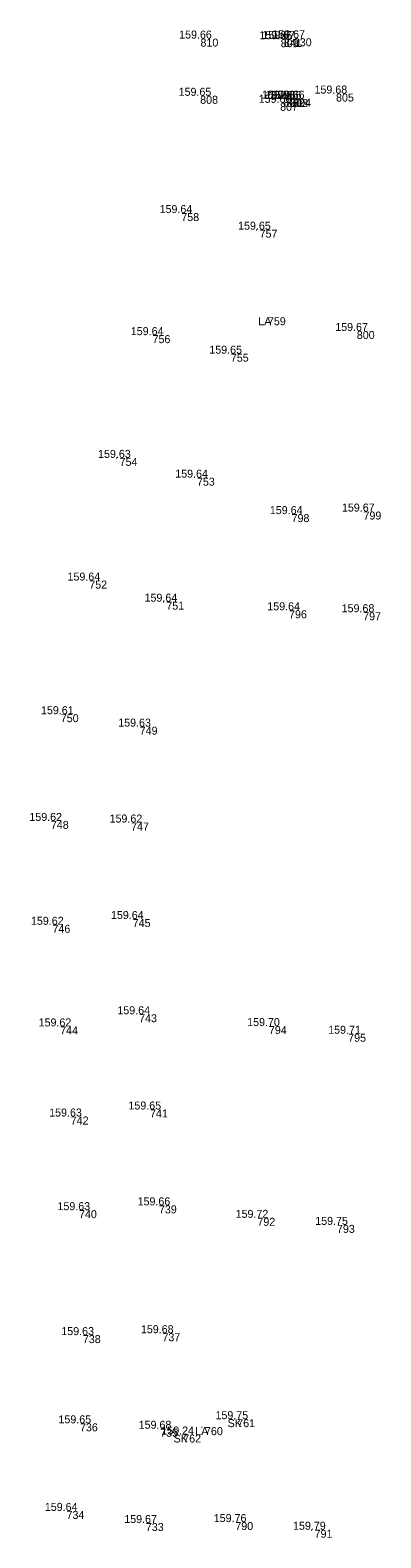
# Model space of a CAD drawing. Extents: x -583198 to -582878, y -1211024 to -1210637.
# Drawn here: x -582888.5 to -582877.53, y -1210734.46 to -1210687.29 of the extents above; entities that cross this region are included whole.
import ezdxf

# ---------------------------------------------------------------- set-up
doc = ezdxf.new("R2010")
doc.units = 0
for name, color, linetype in [('1   Kódy', 7, 'Continuous'), ('4   Body podrobné', 7, 'Continuous'), ('5   Body podrobné - čísla', 7, 'Continuous'), ('6   Body podrobné - výšky', 7, 'Continuous')]:
    doc.layers.add(name, color=color, linetype=linetype)

msp = doc.modelspace()

# ---------------------------------------------------------------- linework, layer by layer
at = {"layer": '4   Body podrobné'}
for p, q in [((-582883.26, -1210687.55), (-582883.259, -1210687.55)), ((-582880.75, -1210687.57), (-582880.749, -1210687.57)), ((-582880.65, -1210687.56), (-582880.649, -1210687.56)), ((-582880.34, -1210687.54), (-582880.339, -1210687.54)), ((-582883.27, -1210689.34), (-582883.269, -1210689.34)), ((-582880.77, -1210689.56), (-582880.769, -1210689.56)), ((-582880.67, -1210689.43), (-582880.669, -1210689.43)), ((-582880.56, -1210689.44), (-582880.559, -1210689.44)), ((-582880.45, -1210689.44), (-582880.449, -1210689.44)), ((-582880.36, -1210689.43), (-582880.359, -1210689.43)), ((-582879.02, -1210689.27), (-582879.019, -1210689.27)), ((-582883.86, -1210693.01), (-582883.859, -1210693.01)), ((-582881.41, -1210693.53), (-582881.409, -1210693.53)), ((-582881.15, -1210696.27), (-582881.149, -1210696.27)), ((-582878.37, -1210696.7), (-582878.369, -1210696.7)), ((-582884.76, -1210696.83), (-582884.759, -1210696.83)), ((-582882.31, -1210697.41), (-582882.309, -1210697.41)), ((-582885.79, -1210700.67), (-582885.789, -1210700.67)), ((-582883.37, -1210701.29), (-582883.369, -1210701.29)), ((-582878.16, -1210702.35), (-582878.159, -1210702.35)), ((-582880.41, -1210702.43), (-582880.409, -1210702.43)), ((-582886.74, -1210704.51), (-582886.739, -1210704.51)), ((-582884.33, -1210705.17), (-582884.329, -1210705.17)), ((-582880.49, -1210705.44), (-582880.489, -1210705.44)), ((-582878.17, -1210705.5), (-582878.169, -1210705.5)), ((-582887.63, -1210708.69), (-582887.629, -1210708.69)), ((-582885.16, -1210709.08), (-582885.159, -1210709.08)), ((-582887.94, -1210712.03), (-582887.939, -1210712.03)), ((-582885.43, -1210712.08), (-582885.429, -1210712.08)), ((-582885.38, -1210715.1), (-582885.379, -1210715.1)), ((-582887.89, -1210715.28), (-582887.889, -1210715.28)), ((-582885.18, -1210718.08), (-582885.179, -1210718.08)), ((-582887.65, -1210718.46), (-582887.649, -1210718.46)), ((-582881.12, -1210718.45), (-582881.119, -1210718.45)), ((-582878.64, -1210718.69), (-582878.639, -1210718.69)), ((-582884.84, -1210721.06), (-582884.839, -1210721.06)), ((-582887.32, -1210721.28), (-582887.319, -1210721.28)), ((-582884.56, -1210724.06), (-582884.559, -1210724.06)), ((-582887.06, -1210724.21), (-582887.059, -1210724.21)), ((-582881.48, -1210724.45), (-582881.479, -1210724.45)), ((-582878.99, -1210724.67), (-582878.989, -1210724.67)), ((-582886.94, -1210728.12), (-582886.939, -1210728.12)), ((-582884.45, -1210728.06), (-582884.449, -1210728.06)), ((-582887.03, -1210730.88), (-582887.029, -1210730.88)), ((-582884.52, -1210731.05), (-582884.519, -1210731.05)), ((-582883.12, -1210731), (-582883.119, -1210731)), ((-582882.11, -1210730.75), (-582882.109, -1210730.75)), ((-582883.8, -1210731.23), (-582883.799, -1210731.23)), ((-582887.45, -1210733.62), (-582887.449, -1210733.62)), ((-582882.17, -1210733.97), (-582882.169, -1210733.97)), ((-582884.97, -1210734), (-582884.969, -1210734)), ((-582879.69, -1210734.21), (-582879.689, -1210734.21))]:
    msp.add_line(p, q, dxfattribs=at)

# ---------------------------------------------------------------- texts
at = {"layer": '1   Kódy'}
for s, p in [('LA', (-582881.36, -1210696.52)), ('LA', (-582883.33, -1210731.25)), ('SK', (-582882.319, -1210731)), ('SK', (-582884.009, -1210731.48))]:
    msp.add_text(s, height=0.25, dxfattribs=at).set_placement(p)
at = {"layer": '5   Body podrobné - čísla'}
for s, p in [(' 810', (-582883.26, -1210687.8)), (' 809', (-582880.75, -1210687.82)), (' 841', (-582880.65, -1210687.81)), (' 830', (-582880.34, -1210687.79)), (' 808', (-582883.27, -1210689.59)), (' 807', (-582880.77, -1210689.81)), (' 801', (-582880.67, -1210689.68)), (' 802', (-582880.56, -1210689.69)), (' 803', (-582880.45, -1210689.69)), (' 804', (-582880.36, -1210689.68)), (' 805', (-582879.02, -1210689.52)), (' 758', (-582883.86, -1210693.26)), (' 757', (-582881.41, -1210693.78)), (' 759', (-582881.15, -1210696.52)), (' 800', (-582878.37, -1210696.95)), (' 756', (-582884.76, -1210697.08)), (' 755', (-582882.31, -1210697.66)), (' 754', (-582885.79, -1210700.92)), (' 753', (-582883.37, -1210701.54)), (' 799', (-582878.16, -1210702.6)), (' 798', (-582880.41, -1210702.68)), (' 752', (-582886.74, -1210704.76)), (' 751', (-582884.33, -1210705.42)), (' 796', (-582880.49, -1210705.69)), (' 797', (-582878.17, -1210705.75)), (' 750', (-582887.63, -1210708.94)), (' 749', (-582885.16, -1210709.33)), (' 748', (-582887.94, -1210712.28)), (' 747', (-582885.43, -1210712.33)), (' 745', (-582885.38, -1210715.35)), (' 746', (-582887.89, -1210715.53)), (' 743', (-582885.18, -1210718.33)), (' 744', (-582887.65, -1210718.71)), (' 794', (-582881.12, -1210718.7)), (' 795', (-582878.64, -1210718.94)), (' 741', (-582884.84, -1210721.31)), (' 742', (-582887.32, -1210721.53)), (' 739', (-582884.56, -1210724.31)), (' 740', (-582887.06, -1210724.46)), (' 792', (-582881.48, -1210724.7)), (' 793', (-582878.99, -1210724.92)), (' 738', (-582886.94, -1210728.37)), (' 737', (-582884.45, -1210728.31)), (' 736', (-582887.03, -1210731.13)), (' 735', (-582884.52, -1210731.3)), (' 760', (-582883.12, -1210731.25)), (' 761', (-582882.11, -1210731)), (' 762', (-582883.8, -1210731.48)), (' 734', (-582887.45, -1210733.87)), (' 790', (-582882.17, -1210734.22)), (' 733', (-582884.97, -1210734.25)), (' 791', (-582879.69, -1210734.46))]:
    msp.add_text(s, height=0.25, dxfattribs=at).set_placement(p)
at = {"layer": '6   Body podrobné - výšky'}
for s, p in [('159.66', (-582883.835, -1210687.55)), ('159.66', (-582881.325, -1210687.57)), ('159.67', (-582881.232, -1210687.56)), ('159.67', (-582880.922, -1210687.54)), ('159.65', (-582883.851, -1210689.34)), ('159.68', (-582879.601, -1210689.27)), ('159.66', (-582881.345, -1210689.56)), ('159.66', (-582881.245, -1210689.43)), ('159.66', (-582881.135, -1210689.44)), ('159.66', (-582881.025, -1210689.44)), ('159.66', (-582880.935, -1210689.43)), ('159.64', (-582884.447, -1210693.01)), ('159.65', (-582881.991, -1210693.53)), ('159.64', (-582885.347, -1210696.83)), ('159.67', (-582878.952, -1210696.7)), ('159.65', (-582882.891, -1210697.41)), ('159.63', (-582886.371, -1210700.67)), ('159.64', (-582883.957, -1210701.29)), ('159.64', (-582880.997, -1210702.43)), ('159.67', (-582878.742, -1210702.35)), ('159.64', (-582887.327, -1210704.51)), ('159.64', (-582884.917, -1210705.17)), ('159.64', (-582881.077, -1210705.44)), ('159.68', (-582878.751, -1210705.5)), ('159.61', (-582888.157, -1210708.69)), ('159.63', (-582885.741, -1210709.08)), ('159.62', (-582888.521, -1210712.03)), ('159.62', (-582886.011, -1210712.08)), ('159.62', (-582888.471, -1210715.28)), ('159.64', (-582885.967, -1210715.1)), ('159.64', (-582885.767, -1210718.08)), ('159.62', (-582888.231, -1210718.46)), ('159.70', (-582881.707, -1210718.45)), ('159.71', (-582879.173, -1210718.69)), ('159.63', (-582887.901, -1210721.28)), ('159.65', (-582885.421, -1210721.06)), ('159.63', (-582887.641, -1210724.21)), ('159.66', (-582885.135, -1210724.06)), ('159.72', (-582882.068, -1210724.45)), ('159.75', (-582879.578, -1210724.67)), ('159.68', (-582885.031, -1210728.06)), ('159.63', (-582887.521, -1210728.12)), ('159.65', (-582887.611, -1210730.88)), ('159.75', (-582882.698, -1210730.75)), ('159.68', (-582885.101, -1210731.05)), ('159.24', (-582884.392, -1210731.23)), ('159.64', (-582888.037, -1210733.62)), ('159.67', (-582885.552, -1210734)), ('159.76', (-582882.752, -1210733.97)), ('159.79', (-582880.272, -1210734.21))]:
    msp.add_text(s, height=0.25, dxfattribs=at).set_placement(p)

doc.saveas('drawing.dxf')
